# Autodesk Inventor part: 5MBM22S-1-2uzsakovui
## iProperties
Created: 2006-11
Part Number: 5MBM22S-1-2uzsakovui
Document SubType Name: Modeling
Designer: Darius
Author: Darius
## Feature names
1. Base1
